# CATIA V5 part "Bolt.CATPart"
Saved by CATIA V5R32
Part number: bolt
Bounding box of the stored display mesh (mm): x -86.603 to 86.603, y -100 to 100, z 0 to 450
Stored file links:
  D:\PROJECTS\Project 2022\CATIA V5 6R 2022\Resources\Part Files\c16_catia_v5_6r2022_prt\Screw Joint-(Fig16-22)\Bolt.CATPart
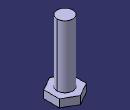
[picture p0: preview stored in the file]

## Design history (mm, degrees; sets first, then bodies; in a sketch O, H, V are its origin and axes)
Body1 (main body)
  Sketch1 on xy-plane, origin (0, 0, 0), H (1, 0, 0), V (0, 1, 0)
    point P1 (86.6025, -50)
    point P2 (86.6025, 50)
    point P3 (0, 100)
    point P4 (-86.6025, 50)
    point P5 (-86.6025, -50)
    point P6 (0, -100)
    point P7 (86.6025, 0)
    line L1 (86.6025, -50) -> (86.6025, 50)
    line L2 (86.6025, 50) -> (0, 100)
    line L3 (0, 100) -> (-86.6025, 50)
    line L4 (-86.6025, 50) -> (-86.6025, -50)
    line L5 (-86.6025, -50) -> (0, -100)
    line L6 (0, -100) -> (86.6025, -50)
    construction line L7 (0, 0) -> (86.6025, 0)
    construction circle A1 centre (0, 0) radius 100
    construction arc A2 centre (-86.6025, -50) radius 100 from (-86.6025, 50) to (0, -100) cw
    construction arc A3 centre (86.6025, 50) radius 100 from (0, 100) to (86.6025, -50) ccw
    radius A1 = 100
    horizontal: L7 H
    coincidence: A1 P1, A1 P2, A1 P3, A1 P4, A1 P5, A1 P6, A2 O, A3 O
    midpoint: P7 L1
    parallelism: L1 L4, L2 L5, L3 L6
    vertical: L4 V, L1 V
  Pad1: profile Sketch1, direction (0, 0, 1), length 50
  Sketch2 on end face of Pad1, origin (0, 0, 50), H (1, 0, 0), V (0, 1, 0)
    circle A1 centre (0, 0) radius 50
    point P1 (0, 50)
    radius A1 = 50
    coincidence: A1 P1, P1 V
  Pad2: profile Sketch2, direction (0, 0, 1), length 400
  Thread1: diameter 100, depth 400, pitch 1, on face of Pad2 from Sketch2.A1, from end face of Pad2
